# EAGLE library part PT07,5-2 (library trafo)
TRANSFORMER 1 primary winding, temp. protection fuse, 2 secondary windings, mounting holes BLOCK
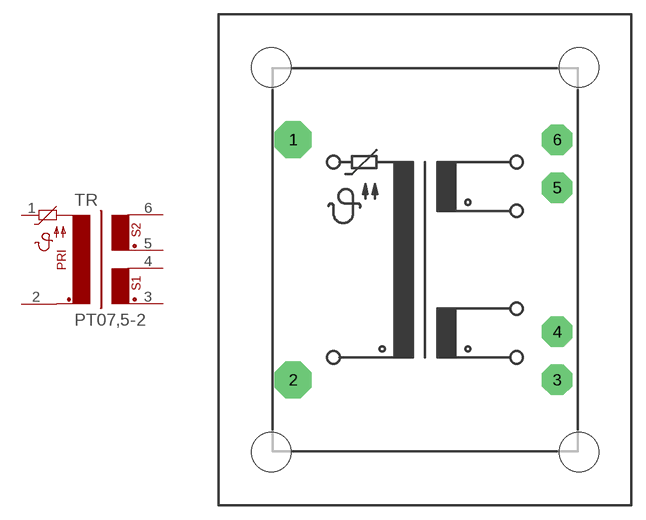
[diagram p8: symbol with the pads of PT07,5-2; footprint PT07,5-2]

Designator prefix TR

## PT07,5-2  [PT07,5-2]
1  1  pas
2  2  pas
3  3  pas
4  4  pas
5  5  pas
6  6  pas

## Footprint PT07,5-2 (pad centres in mm)
TRANSFORMER 1 primary winding, 2 secondary windings, temp. protection fuse, mounting holes
drill 1.397 pad 3.81 octagon: 1 -13.741,12.497; 2 -13.741,-12.497
drill 1.397 pad 3.175 octagon: 3 13.741,-12.497; 4 13.741,-7.493; 5 13.741,7.493; 6 13.741,12.497
hole 4.115 at -16.002,-19.99
hole 4.115 at 16.002,-19.99
hole 4.115 at 16.002,19.99
hole 4.115 at -16.002,19.99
